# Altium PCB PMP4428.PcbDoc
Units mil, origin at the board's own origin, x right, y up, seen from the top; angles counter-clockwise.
Board outline 2350 x 1550 mil, 2 copper layers (Top Layer, Bottom Layer); 70 components, 37 nets, 194 pads, 94 vias.
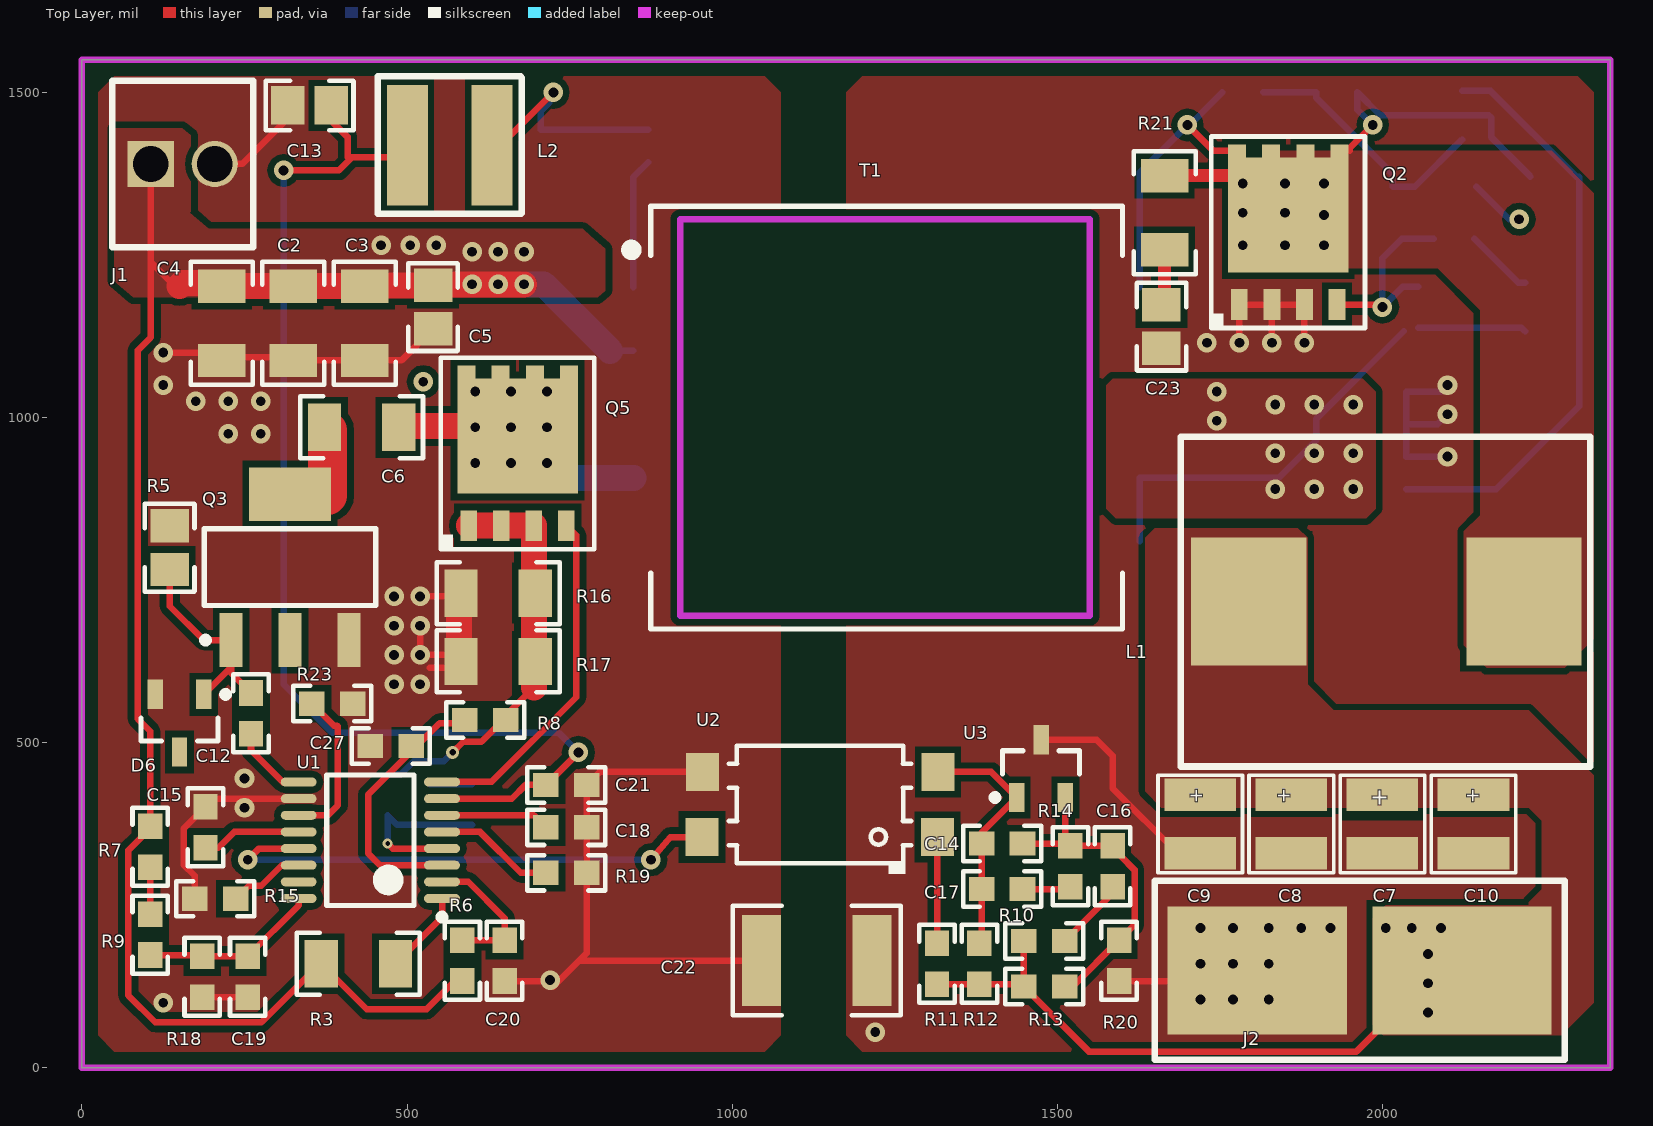
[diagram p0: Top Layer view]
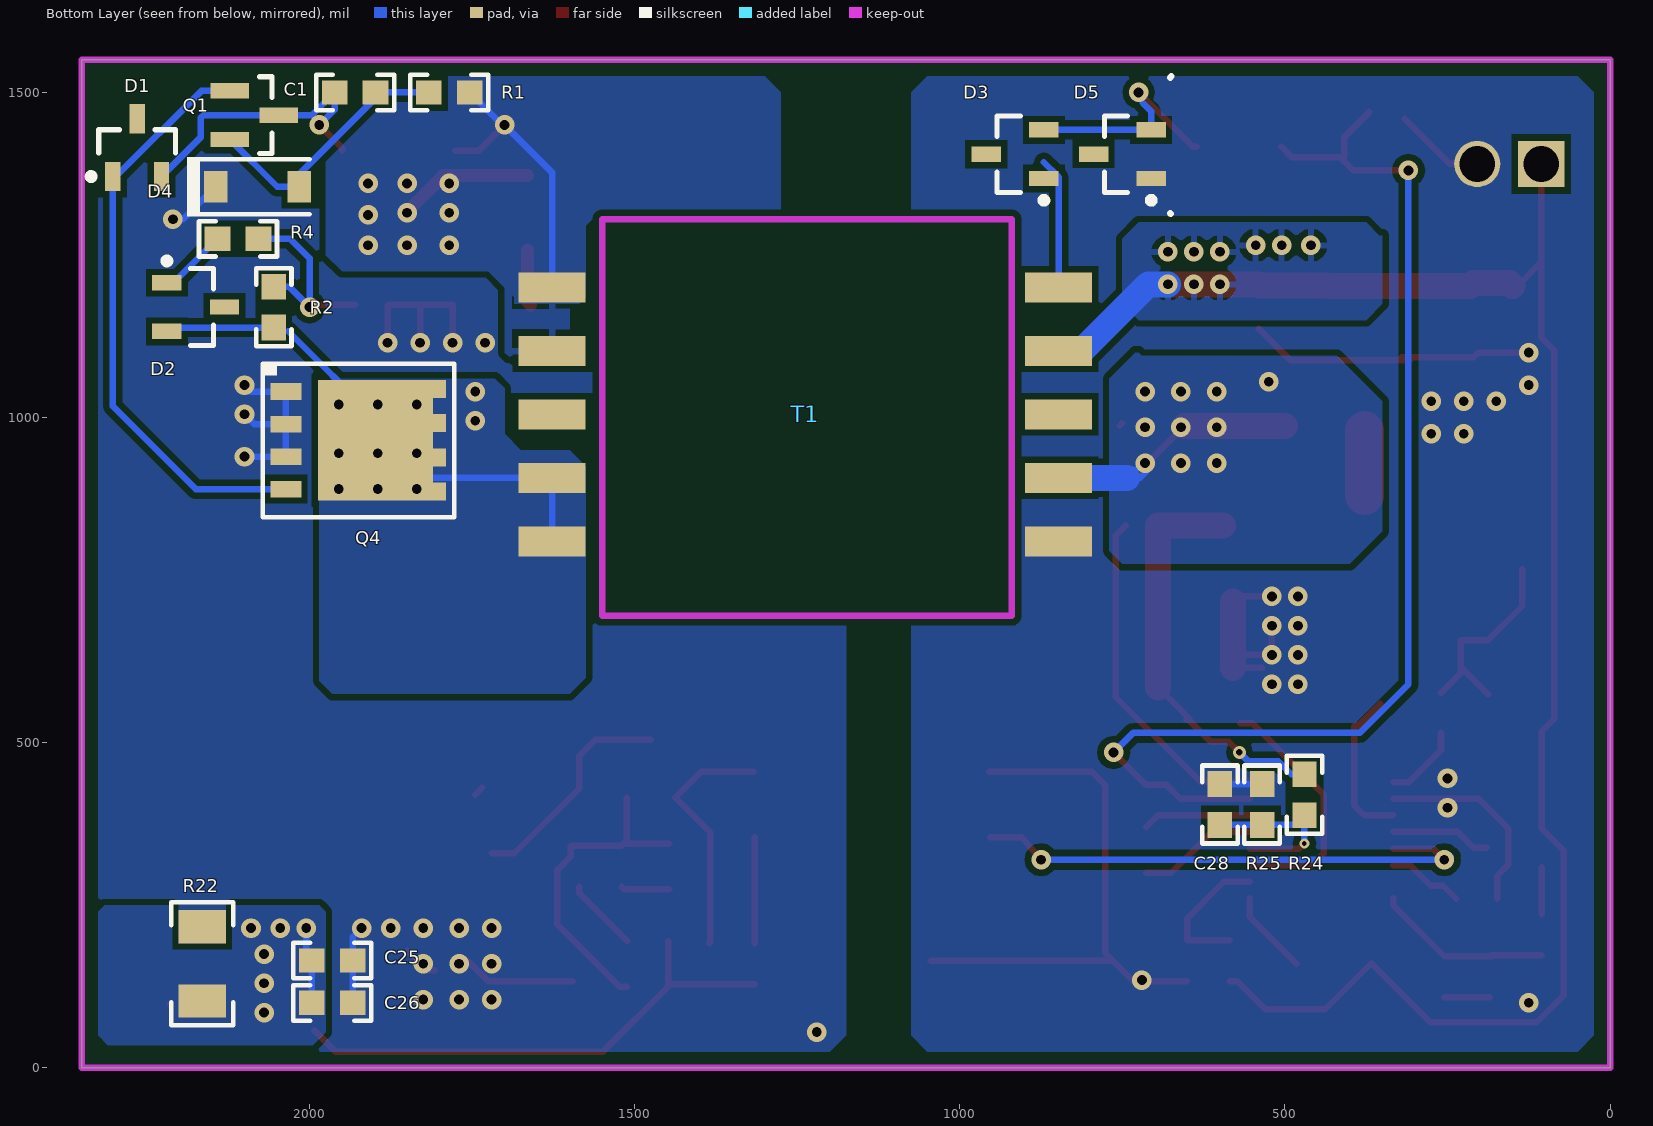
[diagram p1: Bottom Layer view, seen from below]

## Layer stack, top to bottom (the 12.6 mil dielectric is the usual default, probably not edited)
Top Layer: signal copper 1.4
Dielectric: dielectric 12.6, FR-4, Dk 4.8
Bottom Layer: signal copper 1.4

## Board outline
0,0 0,1550 2350,1550 2350,0

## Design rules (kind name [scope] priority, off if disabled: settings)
Clearance [All] p1: gap=10
FabricationTestPointUsage TestPointUsage [All] p1: valid=0 allowmultiple=FALSE
FabricationTestpoint Testpoint [All] p1: side=3 testpointundercomponent=TRUE minsize=40 maxsize=100 preferedsize=60 minholesize=0 maxholesize=40 preferedholesize=32 testpointgrid=1 allowsidetop=TRUE allowsidebottom=TRUE usegrid=TRUE gridtolerance=0.01
PolygonConnect [All] p1: connectstyle=Direct reliefconductorwidth=10 reliefentries=4 polygonreliefangle="90 Angle" airgapwidth=10
RoutingVias [All] p1: holewidth=28 width=50 viastyle="Through Hole" minholewidth=28 minwidth=50 maxholewidth=28 maxwidth=50
SilkscreenOverComponentPads [All] p1: minsilkscreentomaskgap=10
SolderMaskExpansion [All] p1: expansion=4
Width [All] p1: maxlimit=100 minlimit=10 preferedwidth=10
25 further rules are at their usual default settings.

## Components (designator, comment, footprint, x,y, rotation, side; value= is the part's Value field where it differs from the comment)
C1 "Cap" 0603 1930,1500 r0 bottom
C2 "Cap" 1206 325,1145 r270 top
C3 "Cap" 1206 435,1145 r270 top
C4 "Cap" 1206 215,1145 r270 top
C5 "Cap" 0805 540,1170 r270 top
C6 "Cap" 1206 430,985 r180 top
C7 "470uF/6.3V" "POSCAP B2E size" 1940,445 r270 top
C8 "470uF/6.3V" "POSCAP B2E SIZE" 1800,445 r270 top
C9 "470uF/6.3V" "POSCAP B2E SIZE" 1660,445 r270 top
C10 "470uF/6.3V" "POSCAP B2E SIZE" 2080,445 r270 top
C12 "Cap" 0603 260,545 r270 top
C13 "Cap" 0805 350,1480 r0 top
C14 "Cap" 0603 1415,345 r180 top
C15 "Cap" 0603 190,370 r270 top
C16 "Cap" 0603 1585,310 r270 top
C17 "Cap" 0603 1415,275 r180 top
C18 "Cap" 0603 745,370 r180 top
C19 "Cap" 0603 255,140 r90 top
C20 "Cap" 0603 650,165 r90 top
C21 "Cap" 0603 745,435 r180 top
C22 "Cap" 1812_HV 1130,165 r180 top
C23 "Cap" 0805 1660,1140 r90 top
C25 "Cap" 0603 1965,165 r0 bottom
C26 "Cap" 0603 1965,100 r0 bottom
C27 "Cap" 0603 475,495 r0 top
C28 "Cap" 0603 600,405 r270 bottom
D1 "BAS16" SOT-23_N 2265,1415 r90 bottom
D2 "BAS16" SOT-23_N 2175,1170 r180 bottom
D3 "BAS16" SOT-23_N 915,1405 r0 bottom
D4 "BZT52C10" SOD-123 2080,1355 r180 bottom
D5 "BAS16" SOT-23_N 750,1405 r0 bottom
D6 "BAS16" SOT-23_N 150,530 r270 top
J1 "" Connector 155,1390 r0 top
J2 "" "J2 CONNECTOR" 1965,150 r0 top
L1 "7443551111" L1 2310,615 r180 top
L2 "LPS4414" L2 465,1515 r0 top
Q1 "MMBTA06" SOT-23 2085,1465 r180 bottom
Q2 "CSD17552" PG-TDSON-8 1855,1285 r90 top
Q3 "IRFL9110" SOT223_L 320,770 r90 top
Q4 "CSD17552" PG-TDSON-8 1925,965 r180 bottom
Q5 "CSD19533" PG-TDSON-8 670,945 r90 top
R1 "Res1" 0603 1785,1500 r180 bottom
R2 "Res1" 0603 2055,1170 r270 bottom
R3 "Res1" 1206 425,160 r180 top
R4 "Res1" 0603 2110,1275 r0 bottom
R5 "Res1" 0805 135,800 r270 top
R6 "Res1" 0603 585,165 r90 top
R7 "Res1" 0603 105,340 r90 top
R8 "Res1" 0603 620,535 r0 top
R9 "Res1" 0603 105,205 r90 top
R10 "Res1" 0603 1480,195 r180 top
R11 "Res1" 0603 1315,160 r270 top
R12 "Res1" 0603 1380,160 r270 top
R13 "Res1" 0603 1480,125 r180 top
R14 "Res1" 0603 1520,310 r270 top
R15 "Res1" 0603 205,260 r0 top
R16 "Res1" 1206 640,730 r0 top
R17 "Res1" 1206 640,625 r0 top
R18 "Res1" 0603 185,140 r90 top
R19 "Res1" 0603 745,300 r180 top
R20 "Res1" 0603 1595,165 r90 top
R21 "Res1" 1206 1665,1315 r90 top
R22 "Res1" 1206 2165,160 r270 bottom
R23 "Res1" 0603 385,560 r0 top
R24 "Res1" 0603 470,420 r270 bottom
R25 "Res1" 0603 535,405 r90 bottom
T1 "ACF Transformer" WURTH_750313995 1250,1005 r270 top
U1 "LM5025A" PW0016A_L 443.5,350 r180 top
U2 "FOD817A" N04C 1135,405 r180 top
U3 "TL431AIDBZ" SOT-23_N 1475,460 r90 top

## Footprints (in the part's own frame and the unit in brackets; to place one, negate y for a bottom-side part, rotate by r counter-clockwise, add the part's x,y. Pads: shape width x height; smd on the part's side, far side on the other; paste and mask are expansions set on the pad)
0603 [mm]
  rect 1x0.95 smd: 1(-0.8,0) 2(0.8,0)
  silkscreen extent -1.52,-0.69 1.52,0.69, body extent -0.87,-0.47 0.87,0.47, height 0.85
0805 [mm]
  rect 1.3x1.5 smd: 1(-0.85,0) 2(0.85,0)
  silkscreen extent -1.72,-0.97 1.72,0.97, body extent -1.1,-0.72 1.1,0.72, height 1.1
1206 [mm]
  rect 1.3x1.85 smd: 1(-1.45,0) 2(1.45,0)
  silkscreen extent -2.4,-1.21 2.4,1.21, body extent -1.7,-0.9 1.7,0.9, height 1.35
1812_HV [mil]
  rect 60x140 smd: 1(-85,0) 2(85,0)
  silkscreen extent -129,-84 129,84, body extent -94,-67 94,67, height 53
Connector [mm]
  rect 1.8x1.8 hole 1.4: 1(-1.25,0)
  round 1.8 hole 1.4: 2(1.25,0)
  silkscreen extent -2.75,-3.25 2.75,3.25
"J2 CONNECTOR" [mm]
  rect 7x5 smd: 1(-4,0) 2(4,0)
  silkscreen extent -8,-3.5 8,3.5
L1 [mm]
  rect 4.5x5 smd: 1(2.35,-2.6) 2(13.1,-2.6)
  silkscreen extent -0.25,-9.03 15.75,3.85
L2 [mm]
  rect 1.6x4.7 smd: 1(0.9,-2.45) 2(4.2,-2.45)
  silkscreen extent -0.25,-5.13 5.38,0.25
N04C [mm] "FAIRCHILD"
  rect 1.3x1.5 smd mask+0.065: 1(-4.587,1.27) 2(-4.612,-1.27) 3(4.588,-1.27) 4(4.613,1.27)
  silkscreen extent -3.56,-2.3 3.56,2.72, body extent -5.08,-2.3 5.08,2.3, height 3.87
PG-TDSON-8 [mm]
  rect 1.2x0.65 smd: 1(-2.825,1.905) 2(-2.825,0.635) 3(-2.825,-0.635) 4(-2.825,-1.905)
  rect 0.5x0.7 smd: 5(3.175,-2) 6(3.175,-0.675) 7(3.175,0.675) 8(3.175,2)
  rect 4.5x4.7 smd paste-2.25: 9(0.675,0)
  silkscreen extent -3.74,-3 3.74,3, body extent -3.17,-2.9 3.17,2.9, height 1.1
"POSCAP B2E size" [mil] "B2E size (3.5 x 2.8 x 1.9mm)"
  rect 50x110 smd: 1(25,60) 2(115,60)
  silkscreen extent -5,-5 145,125
"POSCAP B2E SIZE" [mil]
  rect 50x110 smd: 1(25,60) 2(115,60)
  silkscreen extent -5,-5 145,125
PW0016A_L [mm]
  oval 1.4x0.35 smd: 1(-2.8,2.275) 2(-2.8,1.625) 3(-2.8,0.975) 4(-2.8,0.325) 5(-2.8,-0.325) 6(-2.8,-0.975) 7(-2.8,-1.625) 8(-2.8,-2.275) 9(2.8,-2.275) 10(2.8,-1.625) 11(2.8,-0.975) 12(2.8,-0.325) 13(2.8,0.325) 14(2.8,0.975) 15(2.8,1.625) 16(2.8,2.275)
  silkscreen extent -2.93,-2.55 1.7,3.12, body extent -2.25,-2.55 2.25,2.55, height 1.2
SOD-123 [mm]
  rect 0.915x1.22 smd: 1(-1.637,0) 2(1.637,0)
  silkscreen extent -2.74,-1.17 2.03,1.17, body extent -1.93,-0.9 1.93,0.9, height 1.35
SOT223_L [mm]
  rect 2.1x0.9 smd: 1(-2.85,2.3) 2(-2.85,-2.3) ""(-2.85,0)
  rect 2.1x3.2 smd: 3(2.85,0)
  silkscreen extent -2.97,-3.35 1.5,3.42, body extent -1.85,-3.35 1.85,3.35, height 1.7
SOT-23 [mm]
  rect 1.5x0.6 smd: 1(-0.95,0.95) 2(-0.95,-0.95) 3(0.95,0)
  silkscreen extent 0.2,-1.5 0.7,1.5, body extent -1.16,-1.45 1.21,1.45, height 1
SOT-23_N [mm]
  rect 1.15x0.6 smd: 1(-1.125,0.95) 2(-1.125,-0.95) 3(1.125,0)
  silkscreen extent -1.25,-1.5 0.7,1.93, body extent -0.7,-1.5 0.7,1.5, height 1.1
WURTH_750313995 [mm]
  rect 1.17x2.62 smd far side: 1(-4.96,-10.212) 2(-2.48,-10.212) 3(0,-10.212) 4(2.48,-10.212) 5(4.96,-10.212) 6(4.96,9.577) 7(2.48,9.577) 8(0,9.577) 9(-2.48,9.577) 10(-4.96,9.577)
  Keep-Out Layer lines w0.254: 7.874,-8.382 7.874,7.62 -7.62,7.62 -7.62,-8.382 7.874,-8.382
  silkscreen extent -8.13,-10.49 8.38,8.9, body extent -5.3,-10.93 5.3,10.3, height 1.2

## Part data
C1 C2 C3 C4 C5 C6 C12 C13 C14 C15 C16 C17 C18 C19 C20 C21 C22 C23 C25 C26 C27 C28: "Capacitor"
C7 C8 C9 C10: library part "Cap Pol1", "Polarized Capacitor (Radial)"
D1 D2 D3 D5 D6: library part Diode, "Default Diode"
D4: library part "D Zener", "Zener Diode"
J1 J2: library part Connector, "Connector"
L1: library part "Inductor Iron", "L*W*H 13mm*12.8*6.2mm"
L2: library part "Inductor Iron", "L*W*H 4.7mm*4.7*1.4mm"
Q1: library part 2N3904, "NPN General Purpose Amplifier"
Q2 Q4: library part CSD19533, "NPN MOSFET"
Q3: library part PMOSFET, "PNP MOSFET"
Q5: "NPN MOSFET"
R1 R2 R3 R4 R5 R6 R7 R8 R9 R10 R11 R12 R13 R14 R15 R16 R17 R18 R19 R20 R21 R22 R23 R24 R25: "Resistor"
T1: "EFD15(TP5)"
U1: "Active Clamp Voltage Mode PWM Controller"
U2: library part Optoisolator1, "4-Pin Phototransistor Optocoupler"
U3: "PRECISION PROGRAMMABLE REFERENCE, DBZ0003A"

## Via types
v1: diameter 30, hole 15, Top Layer to Bottom Layer, 92 vias
v2: diameter 20, hole 10, Top Layer to Bottom Layer, 1 vias
v3: diameter 15, hole 7, Top Layer to Bottom Layer, 1 vias

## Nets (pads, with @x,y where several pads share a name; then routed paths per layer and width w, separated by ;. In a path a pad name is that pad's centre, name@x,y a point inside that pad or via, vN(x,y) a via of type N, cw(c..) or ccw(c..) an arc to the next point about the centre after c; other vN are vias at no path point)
5V: C7.1 C8.1 C9.1 C10.1 C25.2 C26.2 J2.2 L1.2 R10.2 R11.2 R12.2 R13.2 R22.2 | length 956.4
  Top Layer w10: R11.2 R12.2 1445,128.5 R13.2 ; R10.2 R13.2 ; C9.1@1734.25,430.75 C9.1@1745,420 ; J2.2@1993.11,58.11 1960,25 1548.5,25 R13.2 ; J2.2@1993.11,150 J2.2@1993.11,165 ; J2.2@2212.87,95.79 J2.2@2215,97.91
  Bottom Layer w10: C26.2 C25.2 2005,173.5 v1(2005,215)
  other v1: 2070,85 2070,130 2070,175 2045,215 2090,215
5VGND: C7.2 C8.2 C9.2 C10.2 C22.1 C23.1 C25.1 C26.1 D4.1 J2.1 Q2.1 Q2.2 Q2.3 Q4.1 Q4.2 Q4.3 R20.1 R22.1 U3.3 | length 1361.2
  Top Layer w10: U3.3 1560.71,504.29 1585,480 1585,430 1685,330 C9.2 ; R20.1 1725.39,133.5 J2.1@1756.89,165 ; v1(1780,1115) Q2.1 Q2.2 ; J2.1 1820,150 J2.1@1850,180 ; v1(1830,1115) Q2.2 ; v1(1880,1115) Q2.3 Q2.2
  Bottom Layer w10: v1(1920,215) 1933.5,201.5 C25.1 C26.1 ; v1(2100,940) Q4.3 Q4.2 ; v1(2100,1005) 2085,990 Q4.2 ; v1(2100,1050) 2090,1040 Q4.1 Q4.2 ; D4.1 2194.47,1305 v1(2210,1305)
  other v1: 1220,55 1720,105 1770,105 1825,105 1720,160 1770,160 1825,160 1720,215 1770,215 1825,215 1875,215 1730,1115
GND: C2.2 C3.2 C4.2 C5.2 C13.1 C15.1 C18.1 C19.1 C20.1 C21.1 C22.2 C27.1 C28.1 D5.1 D6.2 J1.2 Q3.2 R5.1 R15.1 R16.1 R17.1 R18.1 R19.1 R23.2 R25.2 T1.5 U1.10 U2.3 | length 2209.6
  Top Layer w10: v1(125,1100) 202.91,1100 210,1092.91 320,1092.91 C2.2 ; R15.1 173.5,295.4 156.3,312.61 156.3,367.8 C15.1 202.48,413.98 U1.10 ; R18.1 C19.1 ; J1.2 246.54,1390 C13.1@315.77,1459.23 ; C2.2@307.91,1087.91 C2.2 ; v1(520,680) v1(520,635) R17.1@562.91,635 ; v1(520,725) R16.1@572.09,725 ; 535,615 R17.1@580,615 ; C5.2 491.38,1087.91 C3.2 C2.2 ; C20.1 v1@706.5,133.5 ; v1@710,135 735,135 ; v1@725,125 776.5,176.5 R19.1 C18.1 C21.1 796.5,455 U2.3 ; 765,165 C22.2
  Top Layer w40: R17.1@580,615 R16.1@580,717.09
  Bottom Layer w10: R25.2 C28.1
  other v1: 125,100 720,135 250,400 250,445 480,590 520,590 480,635 480,680 480,725 225,975 275,975 175,1025 225,1025 275,1025 125,1050
NetC1_1: C1.1 D4.2 Q1.2 R1.1 | length 412.4
  Bottom Layer w10: R1.1 C1.1 1898.5,1491.5 2015.53,1374.47 D4.2 2049.8,1355 Q1.2
NetC1_2: C1.2 D1.2 L1.1 Q1.3 Q2.5 Q2.6 Q2.7 Q2.8 Q2.9 R1.2 R21.2 T1.9 T1.10 | length 1113.5
  Top Layer w10: v1(1700,1450) 1740,1410 Q2.8 ; 1950,1410 1950,1415 v1(1985,1450)
  Top Layer w20: R21.2 1794.49,1372.09 Q2.9
  Bottom Layer w10: T1.10 1627.05,1377.05 v1(1700,1450) 1703.5,1450 R1.2 ; v1(1985,1450) 1961.5,1473.5 C1.2 1996.5,1465 Q1.3 2163.31,1465 2166.93,1461.38 2166.93,1431.38 D1.2
  other v1: 1785,1265 1850,1265 1910,1265 1910,1311.57 1785,1315 1850,1315 1785,1360 1850,1360 1910,1360
NetC2_1: C2.1 C3.1 C4.1 C5.1 J1.1 R3.2 R6.1 R7.2 T1.2 | length 2729.3
  Top Layer w10: J1.1 105.79,1239.21 ; 150,1202.09 142.91,1202.09 105.79,1239.21 ; R6.1 573.5,133.5 530,90 437.91,90 R3.2 366.1,160 276.1,70 112.57,70 71.3,111.27 71.3,334.4 105,368.1 R7.2 105,517.44 85.79,536.65 85.79,1103.21 105.79,1123.21 105.79,1239.21
  Top Layer w40: 150,1202.09 155,1207.09 210,1207.09 C4.1 C2.1 C3.1 436.38,1203.46 C5.1 541.54,1205 v1(680,1205)
  Bottom Layer w10: T1.2@812.36,1102.64 T1.2
  Bottom Layer w40: v1(680,1205) 710,1205 T1.2@812.36,1102.64
  other v1: 600,1205 640,1205 600,1255 640,1255 680,1255 460,1265 505,1265 545,1265
NetC6_1: C6.1 Q5.5 Q5.6 Q5.7 Q5.8 Q5.9 T1.4 | length 414.3
  Top Layer w10: Q5.9@654.49,987.09 Q5.9 Q5.9@734.21,907.36 ; Q5.9@750,991.57 Q5.9@754.21,987.36
  Top Layer w40: C6.1@500,987.09 Q5.9@654.49,987.09
  Bottom Layer w10: v1@710,920 722.64,907.36 ; 730,920 742.64,907.36
  Bottom Layer w40: 742.64,907.36 T1.4
  other v1: 605,930 660,930 715,930 605,985 660,985 715,985 605,1040 660,1040 715,1040 525,1055
NetC6_2: C6.2 Q3.3 | length 99.9
  Top Layer w60: Q3.3@377.91,880.12 C6.2@377.91,980
NetC12_1: C12.1 D6.1 Q3.1 R5.2 | length 326
  Top Layer w10: R5.2 135,710 187.2,657.8 Q3.1 229.45,616.34 ; D6.1 229.45,616.34 ; C12.1 229.45,607.05 229.45,616.34
NetC12_2: C12.2 U1.9 | length 120
  Top Layer w10: C12.2@260,515 260,488.5 308.94,439.57 U1.9
NetC13_2: C13.2 C21.2 L2.1 U1.7 | length 1830.7
  Top Layer w10: v1(310,1380) 395,1380 415,1400 ; C13.2@370,1470 408.46,1431.54 408.46,1400 415,1400 ; L2.1@505.43,1416.46 488.98,1400 415,1400 ; U1.7 661.17,413.98 682.19,435 C21.2 v1(763.5,485) v1@765,485
  Bottom Layer w10: v1(310,1380) 310,590 385,515 733.5,515 v1(763.5,485)
NetC14_1: C14.1 C16.1 R13.1 R14.1 R20.2 U3.2 | length 502.2
  Top Layer w10: C14.1 R14.1@1516.5,345 ; R13.1 1523.5,125 R20.2 1618.7,220.2 1618.7,304.4 1598.5,324.6 1598.5,341.5 C16.1 R14.1 R14.1@1516.5,345 ; U3.2 1512.4,349.09 R14.1@1516.5,345
NetC14_2: C14.2 C17.2 R12.1 U2.2 U3.1 | length 384.5
  Top Layer w10: U2.2 1398.31,455 U3.1 1383.5,361.61 C14.2 C17.2 1383.5,192.99 R12.1@1385,191.5
NetC15_2: C15.2 U1.12 | length 153.3
  Top Layer w10: C15.2 210,338.5 234.29,362.8 U1.12
NetC16_2: C16.2 R10.1 | length 114
  Top Layer w10: R10.1 1585,268.5 C16.2
NetC17_1: C17.1 R14.2 | length 75
  Top Layer w10: C17.1 1516.5,275 R14.2
NetC18_2: C18.2 U1.6 | length 167.4
  Top Layer w10: U1.6 695.12,388.39 C18.2
NetC19_2: C19.2 R9.1 R18.2 U1.16 | length 271.4
  Top Layer w10: R9.1 R18.2@182.99,173.5 ; R18.2@182.99,171.5 R18.2 C19.2 333.27,249.76 U1.16
NetC20_2: C20.2 R6.2 U1.2 | length 218
  Top Layer w10: U1.2 593.98,286.02 650,230 C20.2 R6.2
NetC23_2: C23.2 R21.1 | length 86.5
  Top Layer w20: C23.2 1665,1178.46 R21.1
NetC27_2: C27.2 R8.1 U1.3 | length 385.4
  Top Layer w10: U1.3 458.39,311.61 440,330 440,420 550,530 568.5,530
NetC28_2: C28.2 R24.2 R25.1 U1.4 | length 266.7
  Top Layer w10: v3(470,345) 477.8,337.2 U1.4
  Bottom Layer w10: v3(470,345) R24.2 485,373.5 R25.1 C28.2
NetD1_1: D1.1 Q1.1 Q4.4 | length 906.8
  Bottom Layer w10: Q4.4 2175,890 2302.4,1017.4 D1.1 2297.92,1370.71 2166.23,1502.4 Q1.1
NetD2_1: D2.1 R4.2 | length 105.8
  Bottom Layer w10: R4.2 2209.09,1207.4 D2.1
NetD2_2: D2.2 Q4.5 Q4.6 Q4.7 Q4.8 Q4.9 R2.2 T1.6 T1.7 | length 782.8
  Bottom Layer w10: T1.6 T1.7 1840.79,907.36 Q4.9 1898.43,998.43 2032.6,1132.6 ; R2.2 2213.39,1138.5 D2.2
  other v1: 1835,890 1895,890 1955,890 1835,945 1895,945 1955,945 1745,995 1835,1020 1895,1020 1955,1020 1745,1040
NetD3_1: D3.1 T1.1 | length 201.7
  Bottom Layer w10: T1.1 847.95,1369.84 870.71,1392.6
NetD3_2: D3.2 D5.2 L2.2 | length 336.1
  Top Layer w10: L2.2@635.35,1416.46 641.46,1416.46 v1(725,1500)
  Bottom Layer w10: 718.79,1483.79 705.71,1470.71 D5.2 D3.2
NetQ2_4: Q2.4 R2.1 R4.1 | length 304
  Top Layer w10: Q2.4 v1@2000,1173.78
  Bottom Layer w10: R2.1 2031.5,1201.5 v1(2000,1170) 2000,1245 2030,1275 R4.1
NetQ5_1: Q5.1 Q5.2 Q5.3 R8.2 R16.2 R17.2 R24.1 | length 632
  Top Layer w10: v2(570,485) 586.3,501.3 614.4,501.3 648.1,535 R8.2 ; R8.2@647.5,537.5 695,585
  Top Layer w40: Q5.1 Q5.2 Q5.3 695,585
  Bottom Layer w10: R24.1 490.4,451.5 510.09,471.18 556.18,471.18 v2(570,485)
NetQ5_4: Q5.4 U1.8 | length 530.3
  Top Layer w10: U1.8 554.17,440 630,440 760,570 760,818.78 Q5.4
NetR3_1: R3.1 U1.1 | length 130.1
  Top Layer w10: R3.1 553.74,231.65 U1.1
NetR7_1: R7.1 R9.2 | length 72
  Top Layer w10: R9.2 R7.1
NetR11_1: R11.1 U2.1 | length 163.5
  Top Layer w10: R11.1@1315.61,191.5 U2.1
NetR15_2: R15.2 U1.14 | length 118.2
  Top Layer w10: R15.2 256.5,280 275.62,280 307.23,311.61 U1.14
NetR19_2: R19.2 U1.5 | length 185.8
  Top Layer w10: U1.5 612.2,362.8 675,300 R19.2
NetR23_1: R23.1 U1.11 | length 242.5
  Top Layer w10: U1.11 378.39,388.39 393.5,403.5 393.5,525 392.2,526.3 387.2,526.3 R23.1
NetU1_13: U1.13 U2.4 | length 811.1
  Top Layer w10: v1(255,320) 272.2,337.2 U1.13 ; v1(875,320) 905,355 U2.4
  Bottom Layer w10: v1@245,325 v1(255,320) v1(875,320)
pads on no net: D1.3 D2.3 D3.3 D5.3 D6.3 Q3. T1.3 T1.8 U1.15

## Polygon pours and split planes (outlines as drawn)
5VGND on Bottom Layer "Bottom Layer-No Net" (solid, remove dead copper, pour order 28): 1200,25 1175,50 1175,1500 1200,1525 2300,1525 2325,1500 2325,50 2300,25 1200,25
5V on Bottom Layer "Bottom Layer-No Net" (solid, remove dead copper, pour order 27): 1995,250 1985,250 1980,245 1975,240 1975,75 1975,55 1990,40 1995,35 2310,35 2325,50 2325,235 2325,240 2315,250 1985,250
NetC2_1 on Bottom Layer "Bottom Layer-No Net" (solid, remove dead copper, pour order 18): 675,1150 385,1150 375,1150 350,1175 350,1280 355,1280 375,1300 725,1300 750,1275 750,1195 750,1175 725,1150 675,1150
NetC1_2 on Bottom Layer "Bottom Layer-No Net" (solid, remove dead copper, pour order 19): 1300,1525 1275,1500 1275,1320 1565,1320 1570,1315 1565,1320 1550,1320 1575,1295 1575,1215 1575,1185 1580,1180 1585,1175 1685,1175 1685,1185 1725,1225 1950,1225 1975,1250 1968.37,1256.63 1968.37,1400 1897.07,1471.3 1843.37,1525 1840,1525 1300,1525
NetD2_2 on Bottom Layer "Bottom Layer-No Net" (solid, remove dead copper, pour order 16): 1790,1060 1715,1060 1700,1045 1700,975 1675,950 1600,950 1575,925 1575,600 1600,575 1965,575 1985,595 1985,865 1985,1040 1965,1060 1715,1060
NetC1_2 on Bottom Layer "Bottom Layer-No Net" (solid, remove dead copper, pour order 25): 1625,1475 1550,1400 1550,1350 1600,1300 1600,1105 1630,1075 1675,1075 1700,1100 1700,1125 1700,1200 1725,1225 1950,1225 1975,1250 1975,1450 1950,1475 1625,1475
NetC6_1 on Bottom Layer "Bottom Layer-No Net" (solid, remove dead copper, pour order 29): 350,1025 350,825 400,775 745,775 750,775 770,795 770,1060 730,1100 725,1100 720,1095 420,1095
GND on Bottom Layer "Bottom Layer-No Net" (solid, remove dead copper, pour order 33): 50,1525 25,1500 25,50 50,25 1050,25 1075,50 1075,1500 1050,1525 50,1525
5VGND on Top Layer "Bottom Layer-No Net" (solid, remove dead copper, pour order 30): 1200,25 1175,50 1175,1500 1200,1525 2300,1525 2325,1500 2325,50 2300,25 1200,25
5VGND on Top Layer "Bottom Layer-No Net" (solid, remove dead copper, pour order 26): 1660,355 1645,340 1645,65 1665,45 1940,45 1945,45 1950,50 1955,55 1955,250 1955,270 1965,280 2195,280 2200,285 2205,290 2205,350 2195,360 1665,360 1660,355
NetC1_2 on Top Layer "Bottom Layer-No Net" (solid, remove dead copper, pour order 24): 1950,1230 2085,1230 2150,1165 2150,850 2125,825 2125,650 2155,620 2160,615 2280,615 2310,645 2325,660 2325,1340 2325,1345 2260,1410 1828.43,1410 1828.43,1346.57 1945,1230
5V on Top Layer "Bottom Layer-No Net" (solid, remove dead copper, pour order 23): 1635,425 1660,400 2225,400 2245,380 2245,325 2245,275 2225,255 2225,250 2005,250 1985,230 1985,220 1985,66.22 1993.11,58.11 2001.22,50 2265,50 2275,50 2325,100 2325,425 2325,450 2225,550 2125,550 1925,550 1885,590 1885,815 1870,830 1800,830 1650,830 1640,820 1635,815 1635,425
NetC2_1 on Top Layer "Bottom Layer-No Net" (solid, remove dead copper, pour order 20): 50,1445 154.54,1445 167.01,1434.26 167.57,1434.26 167.57,1316.22 166.15,1315 195.19,1290 770.15,1290 781.77,1280 805,1260 805,1195 793.38,1185 79.04,1185 50,1210 50,1445
NetD2_2 on Top Layer "Bottom Layer-No Net" (solid, remove dead copper, pour order 17): 1725,1060 1585,1060 1575,1050 1575,865 1575,860 1600,835 1590,845 1585,850 1590,845 1975,845 1990,860 1990,1040 1970,1060 1725,1060
GND on Top Layer "Bottom Layer-No Net" (solid, remove dead copper, pour order 35): 50,1525 25,1500 25,50 50,25 1050,25 1075,50 1075,1500 1050,1525 50,1525

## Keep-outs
Keep-Out Layer:
  lines w10: 0,0 0,1550 2350,1550 2350,0 0,0 ; 920,695 1550,695 1550,1305 920,1305 920,695

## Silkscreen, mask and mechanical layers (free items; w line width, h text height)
Mechanical 16:
  drawing of 1890 lines, arcs and shapes, not listed
  text "1" at -1328.66,19290 h20
  text "2" at 1292,19290 h20
  text "3" at 3911.34,19290 h20
  text "4" at 6538.01,19290 h20
  text "5" at 9162,19290 h20
  text "6" at 11782,19290 h20
  text "7" at 14412,19290 h20
  text "8" at 17032,19290 h20
  text "9" at 19652,19290 h20
  text "10" at 22262,19290 h20
  text "11" at 24902,19290 h20
  text "12" at 27522,19290 h20
  text "A" at -2505.32,16598.01 h20
  text "A" at 28694.68,16598.01 h20
  text "B" at -2498.66,11022 h20
  text "B" at 28701.34,11022 h20
  text "C" at -2498,5452 h20
  text "C" at 28702,5452 h20
  text "D" at -2498,-118 h20
  text "D" at 28702,-118 h20
  text "ENGINEER:" at 24125,-1425 h20
  text "TITLE:" at 25625,-1425 h20
  text "PCB DESIGNER:" at 24125,-1720 h20
  text "DATE:" at 24125,-2025 h20
  text "PART NO.:" at 25625,-2025 h20
  text "REV:" at 27725,-2025 h20
  text "Altium Limited" at 22825,-2125 h20
  text ".PRINT_DATE" at 24175,-2145 h20
  text "12a Rodborough Rd" at 22825,-2225 h20
  text "Frenchs Forest" at 22825,-2325 h20
  text "FILE NAME:" at 24125,-2325 h20
  text "DWG NO:" at 25625,-2325 h20
  text "SCALE:" at 27725,-2325 h20
  text "NSW 2086" at 22825,-2425 h20
  text ".PCB_FILE_NAME_NO_PATH" at 24175,-2445 h20
  text "1" at -1328.66,-2710 h20
  text "2" at 1292,-2710 h20
  text "3" at 3911.34,-2710 h20
  text "4" at 6538.01,-2710 h20
  text "5" at 9162,-2710 h20
  text "6" at 11782,-2710 h20
  text "7" at 14412,-2710 h20
  text "8" at 17032,-2710 h20
  text "9" at 19652,-2710 h20
  text "10" at 22262,-2710 h20
  text "11" at 24902,-2710 h20
  text "12" at 27522,-2710 h20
